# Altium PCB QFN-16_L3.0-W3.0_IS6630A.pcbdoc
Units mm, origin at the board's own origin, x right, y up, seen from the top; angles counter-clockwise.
Board outline 16.55 x 16.1 mm, 2 copper layers (Top Layer, Bottom Layer), stack 0 mm thick; 1 components, 0 nets, 16 pads, 0 vias.
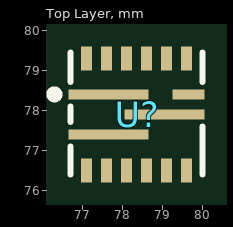
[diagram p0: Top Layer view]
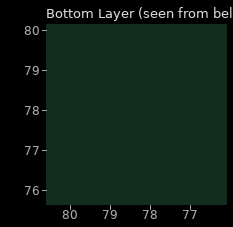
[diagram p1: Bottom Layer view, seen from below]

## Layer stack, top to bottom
Top Layer: signal copper (thickness not stored)
Bottom Layer: signal copper (thickness not stored)

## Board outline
86.4,69.85 69.85,69.85 69.85,85.95 86.4,85.95

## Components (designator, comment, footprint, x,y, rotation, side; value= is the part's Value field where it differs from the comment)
U? "" QFN-16_L3.0-W3.0_IS6630A 78.375,77.9 r0 top

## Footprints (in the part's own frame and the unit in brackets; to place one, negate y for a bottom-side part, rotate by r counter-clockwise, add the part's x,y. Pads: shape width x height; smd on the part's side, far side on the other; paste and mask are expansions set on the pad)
QFN-16_L3.0-W3.0_IS6630A [mm]
  rect 2x0.25 smd: 1(-0.725,0.5) 2(-0.725,-0.5) 9(0.675,0)
  rect 0.28x0.6 smd: 3(-1.275,-1.4) 4(-0.775,-1.4) 5(-0.275,-1.4) 6(0.225,-1.4) 7(0.725,-1.4) 8(1.225,-1.4) 11(1.225,1.4) 12(0.725,1.4) 13(0.225,1.4) 14(-0.275,1.4) 15(-0.775,1.4) 16(-1.275,1.4)
  rect 0.8x0.25 smd: 10(1.275,0.5)
  silkscreen extent -2.17,-1.5 1.62,1.55

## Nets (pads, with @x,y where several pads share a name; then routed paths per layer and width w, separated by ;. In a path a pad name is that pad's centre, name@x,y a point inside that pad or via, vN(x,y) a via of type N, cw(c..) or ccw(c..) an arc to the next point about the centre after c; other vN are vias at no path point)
pads on no net: U?.1 U?.2 U?.3 U?.4 U?.5 U?.6 U?.7 U?.8 U?.9 U?.10 U?.11 U?.12 U?.13 U?.14 U?.15 U?.16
